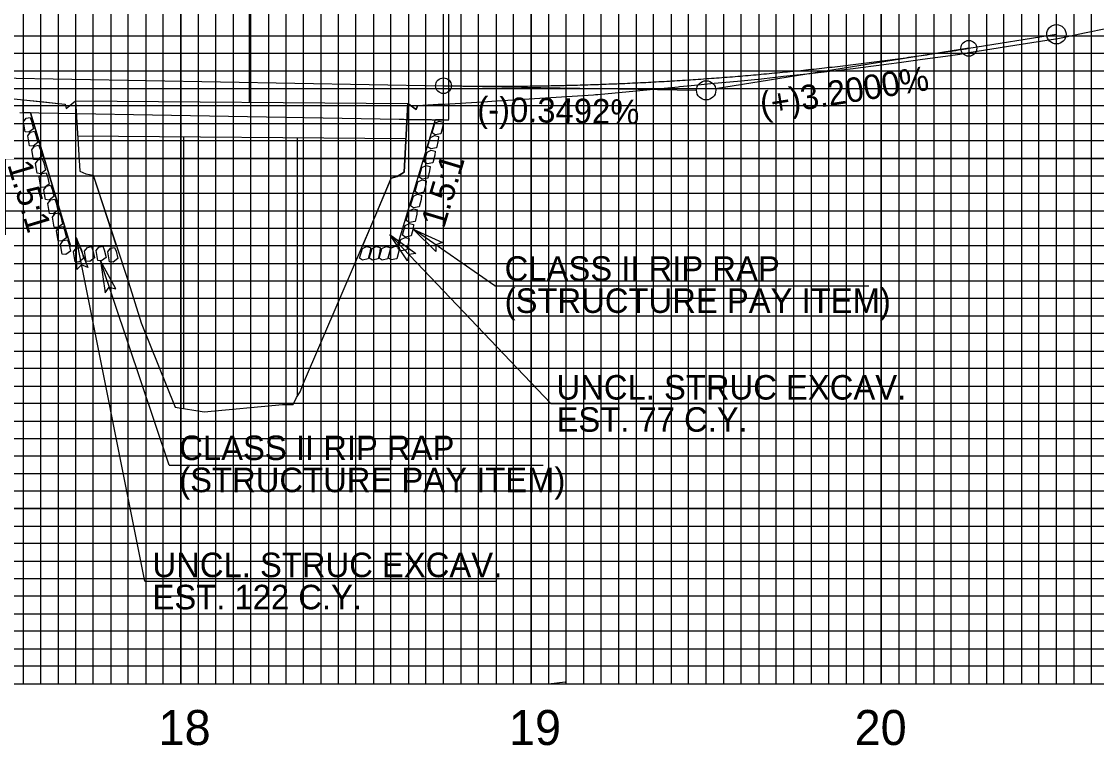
# Model space of a CAD drawing. Extents: x 573926 to 575610, y -51565 to -50465.
# Drawn here: x 574797.3 to 575104.2, y -51007.6 to -50800.8 of the extents above; entities that cross this region are included whole.
import ezdxf

# ---------------------------------------------------------------- set-up
doc = ezdxf.new("R2010")
doc.units = 0
for name, color, linetype in [('Default', 7, 'Continuous'), ('Exist Vertical Profile Ground Line', 7, 'Continuous'), ('Exist Vertical Profile Horizontal Axis Label Major', 7, 'Continuous'), ('Old_Level_1', 7, 'Continuous'), ('Prop Dimension', 7, 'Continuous'), ('Prop Dimension Text', 7, 'Continuous'), ('Prop Roadway Bridge', 7, 'Continuous'), ('Prop Terminator CELL', 7, 'Continuous'), ('Prop Vertical Profile Curve Label', 7, 'Continuous'), ('Prop Vertical Profile Grade', 7, 'Continuous'), ('Prop Vertical Profile Grade Label', 7, 'Continuous'), ('Prop VPI Label', 7, 'Continuous'), ('Sheet DOT Grid CELL', 7, 'Continuous'), ('Sheet Layout Profile Border Port 1', 7, 'Continuous'), ('Sheet Profile CELL', 7, 'Continuous'), ('Sheet Profile Grid Major CELL', 7, 'Continuous'), ('Sheet Profile Grid Middle CELL', 7, 'Continuous'), ('Sheet Profile Grid Minor CELL', 7, 'Continuous')]:
    doc.layers.add(name, color=color, linetype=linetype)

msp = doc.modelspace()

# ---------------------------------------------------------------- linework, layer by layer
at = {"layer": 'Default'}
for p, q in [((574812.68, -50823.46), (574907.64, -50824.23)), ((574813.3, -50833.46), (574907.08, -50834.23)), ((574843.68, -50911.41), (574843.68, -50833.71)), ((574876.14, -50907.67), (574876.14, -50833.97))]:
    msp.add_line(p, q, dxfattribs=at)
msp.add_lwpolyline([(574780.55, -50821.4), (574807.9, -50824.25), (574809.8, -50824.44), (574810.09, -50825.7), (574812.68, -50823.46), (574813.93, -50843.61), (574815.63, -50844.33), (574817.74, -50844.69), (574827.84, -50875.27), (574831.51, -50886.91), (574841.22, -50911.01), (574849.48, -50912.35), (574871.82, -50910.2), (574874.9, -50910.25), (574875.81, -50908.19), (574876.85, -50906.55), (574877.8, -50904.15), (574898.23, -50856.73), (574902.83, -50845.62), (574904.59, -50845.09), (574906.54, -50843.84), (574907.64, -50824.23), (574909.96, -50825.94), (574910.33, -50824.95), (574930.36, -50823.68), (574931.57, -50823.59), (574960.61, -50821.75), (574961.19, -50821.71), (574961.85, -50821.65), (574984.78, -50819.47), (574985.17, -50819.44), (574988.48, -50819.13)], dxfattribs=at)
at = {"layer": 'Exist Vertical Profile Ground Line'}
msp.add_lwpolyline([(574988.48, -50819.13), (574995.08, -50818.5), (575001.69, -50817.87), (575008.61, -50817.21), (575014.9, -50816.5), (575021.5, -50815.76), (575028.11, -50815.02), (575034.71, -50814.27), (575036.85, -50814.03), (575041.31, -50813.42), (575044.95, -50812.92), (575047.92, -50812.51), (575054.52, -50811.61), (575061.13, -50810.71), (575065.23, -50810.14), (575067.73, -50809.74), (575074.34, -50808.69), (575080.94, -50807.64), (575087.55, -50806.59), (575093.15, -50805.69), (575094.15, -50805.48), (575100.76, -50804.12), (575107.36, -50802.75)], dxfattribs=at)
at = {"layer": 'Old_Level_1'}
for p, q in [((574799.88, -50826.92), (574811.29, -50864.95)), ((574904.63, -50864.95), (574915.46, -50828.84)), ((574811.29, -50864.95), (574824.37, -50864.95)), ((574894.69, -50864.95), (574904.63, -50864.95))]:
    msp.add_line(p, q, dxfattribs=at)
for points in [[(574817.74, -50844.69), (574824.37, -50864.95), (574811.29, -50864.95), (574799.88, -50826.92), (574797.78, -50826.88), (574797.78, -50823.2), (574802.78, -50823.72), (574807.9, -50824.25), (574809.8, -50824.44), (574810.09, -50825.7), (574812.68, -50823.46), (574813.93, -50843.61), (574815.63, -50844.33)], [(574902.83, -50845.62), (574894.69, -50864.95), (574904.63, -50864.95), (574915.46, -50828.84), (574917.78, -50828.86), (574917.78, -50824.48), (574910.33, -50824.95), (574909.96, -50825.94), (574907.64, -50824.23), (574906.54, -50843.84), (574904.59, -50845.09)]]:
    msp.add_lwpolyline(points, close=True, dxfattribs=at)
for points in [[(574799.78, -50828.22), (574800.2, -50829.33), (574800.69, -50831.45), (574799.37, -50832.45), (574798.32, -50832.34), (574797.84, -50829.53), (574798.64, -50828.49), (574799.78, -50828.22)], [(574917.68, -50829.58), (574917.56, -50830.76), (574917.04, -50832.88), (574915.41, -50833.17), (574914.52, -50832.61), (574915.36, -50829.88), (574916.54, -50829.3), (574917.68, -50829.58)], [(574801.02, -50832.21), (574801.44, -50833.32), (574801.93, -50835.44), (574800.6, -50836.44), (574799.55, -50836.33), (574799.08, -50833.52), (574799.88, -50832.47), (574801.02, -50832.21)], [(574916.4, -50833.64), (574916.28, -50834.82), (574915.77, -50836.93), (574914.14, -50837.23), (574913.24, -50836.66), (574914.08, -50833.93), (574915.26, -50833.36), (574916.4, -50833.64)], [(574802.19, -50836.15), (574802.61, -50837.26), (574803.1, -50839.38), (574801.77, -50840.37), (574800.72, -50840.27), (574800.24, -50837.45), (574801.04, -50836.41), (574802.19, -50836.15)], [(574915.4, -50837.88), (574915.28, -50839.06), (574914.76, -50841.17), (574913.13, -50841.47), (574912.24, -50840.9), (574913.08, -50838.17), (574914.26, -50837.6), (574915.4, -50837.88)], [(574803.23, -50840.08), (574803.65, -50841.19), (574804.14, -50843.31), (574802.82, -50844.31), (574801.77, -50844.2), (574801.29, -50841.39), (574802.09, -50840.34), (574803.23, -50840.08)], [(574804.34, -50844.02), (574804.76, -50845.13), (574805.25, -50847.25), (574803.92, -50848.24), (574802.87, -50848.13), (574802.39, -50845.32), (574803.2, -50844.28), (574804.34, -50844.02)], [(574913.96, -50842.27), (574913.84, -50843.45), (574913.32, -50845.57), (574911.69, -50845.86), (574910.8, -50845.3), (574911.64, -50842.57), (574912.82, -50841.99), (574913.96, -50842.27)], [(574912.82, -50846.33), (574912.7, -50847.51), (574912.18, -50849.62), (574910.55, -50849.92), (574909.66, -50849.35), (574910.5, -50846.63), (574911.68, -50846.05), (574912.82, -50846.33)], [(574805.63, -50847.6), (574806.05, -50848.71), (574806.54, -50850.83), (574805.21, -50851.82), (574804.16, -50851.71), (574803.68, -50848.9), (574804.48, -50847.86), (574805.63, -50847.6)], [(574911.52, -50850.47), (574911.4, -50851.65), (574910.89, -50853.76), (574909.26, -50854.06), (574908.37, -50853.49), (574909.2, -50850.76), (574910.38, -50850.19), (574911.52, -50850.47)], [(574806.79, -50851.54), (574807.22, -50852.65), (574807.7, -50854.77), (574806.38, -50855.77), (574805.33, -50855.66), (574804.85, -50852.85), (574805.65, -50851.81), (574806.79, -50851.54)], [(574808.09, -50855.46), (574808.51, -50856.57), (574808.99, -50858.69), (574807.67, -50859.68), (574806.62, -50859.58), (574806.14, -50856.76), (574806.94, -50855.72), (574808.09, -50855.46)], [(574910.32, -50854.66), (574910.2, -50855.84), (574909.68, -50857.95), (574908.05, -50858.25), (574907.16, -50857.68), (574908, -50854.95), (574909.18, -50854.38), (574910.32, -50854.66)], [(574809.2, -50859.35), (574809.62, -50860.46), (574810.11, -50862.58), (574808.78, -50863.58), (574807.73, -50863.47), (574807.26, -50860.66), (574808.06, -50859.61), (574809.2, -50859.35)], [(574909.22, -50858.8), (574909.09, -50859.98), (574908.58, -50862.09), (574906.95, -50862.39), (574906.06, -50861.82), (574906.89, -50859.09), (574908.07, -50858.52), (574909.22, -50858.8)], [(574907.97, -50862.79), (574907.84, -50863.97), (574907.33, -50866.08), (574905.7, -50866.38), (574904.81, -50865.81), (574905.64, -50863.08), (574906.82, -50862.51), (574907.97, -50862.79)], [(574810.4, -50863.17), (574810.82, -50864.28), (574811.3, -50866.4), (574809.98, -50867.4), (574808.93, -50867.29), (574808.45, -50864.48), (574809.25, -50863.43), (574810.4, -50863.17)], [(574814.11, -50865.34), (574814.53, -50866.45), (574815.01, -50868.57), (574813.69, -50869.57), (574812.64, -50869.46), (574812.16, -50866.65), (574812.96, -50865.6), (574814.11, -50865.34)], [(574817.26, -50865.13), (574817.68, -50866.24), (574818.17, -50868.36), (574816.84, -50869.35), (574815.79, -50869.25), (574815.32, -50866.43), (574816.12, -50865.39), (574817.26, -50865.13)], [(574820.53, -50864.98), (574820.95, -50866.09), (574821.44, -50868.21), (574820.12, -50869.2), (574819.07, -50869.1), (574818.59, -50866.28), (574819.39, -50865.24), (574820.53, -50864.98)], [(574823.87, -50865.34), (574824.29, -50866.44), (574824.78, -50868.57), (574823.45, -50869.56), (574822.4, -50869.45), (574821.93, -50866.64), (574822.73, -50865.6), (574823.87, -50865.34)], [(574896.97, -50865.37), (574896.85, -50866.55), (574896.33, -50868.66), (574894.7, -50868.96), (574893.81, -50868.39), (574894.65, -50865.66), (574895.83, -50865.09), (574896.97, -50865.37)], [(574899.74, -50865.37), (574899.62, -50866.55), (574899.11, -50868.66), (574897.48, -50868.96), (574896.58, -50868.39), (574897.42, -50865.66), (574898.6, -50865.09), (574899.74, -50865.37)], [(574902.55, -50865.37), (574902.43, -50866.55), (574901.91, -50868.66), (574900.29, -50868.96), (574899.39, -50868.39), (574900.23, -50865.66), (574901.41, -50865.09), (574902.55, -50865.37)], [(574905.13, -50865.29), (574905.01, -50866.47), (574904.49, -50868.59), (574902.86, -50868.88), (574901.97, -50868.32), (574902.8, -50865.59), (574903.99, -50865.01), (574905.13, -50865.29)]]:
    msp.add_lwpolyline(points, dxfattribs=at)
at = {"layer": 'Prop Dimension'}
for p, q in [((575092.78, -50804.5), (575092.78, -50624.54)), ((574919.34, -50819.11), (574919.34, -50664.95)), ((574862.33, -50762.43), (574862.33, -50823.86)), ((574832.53, -50960.67), (574812.89, -50862.56)), ((574902.47, -50861.64), (574948.45, -50909.93)), ((574932.41, -50876.34), (574909.12, -50860.12)), ((574839.5, -50927.53), (574819.85, -50869.19)), ((574932.41, -50876.34), (575039.19, -50876.34)), ((574948.45, -50909.93), (575048, -50909.93)), ((574839.5, -50927.53), (574946.28, -50927.53)), ((574832.53, -50960.67), (574932.69, -50960.67))]:
    msp.add_line(p, q, dxfattribs=at)
at = {"layer": 'Prop Roadway Bridge'}
for p, q in [((574919.34, -50828.87), (574919.34, -50819.11)), ((574796.84, -50826.87), (574905.11, -50828.76))]:
    msp.add_line(p, q, dxfattribs=at)
msp.add_open_spline([(574905.12, -50828.76), (574906.3, -50828.78), (574907.47, -50828.79), (574908.64, -50828.81), (574909.82, -50828.83), (574911, -50828.84), (574912.18, -50828.86), (574913.35, -50828.87), (574914.53, -50828.88), (574915.71, -50828.89), (574916.89, -50828.89), (574918.07, -50828.9), (574919.25, -50828.9), (574919.28, -50828.9), (574919.31, -50828.9), (574919.34, -50828.9)], degree=3, dxfattribs=at)
at = {"layer": 'Prop Terminator CELL'}
for points in [[(574813.13, -50871.69), (574812.89, -50862.56), (574816.23, -50871.12), (574814.44, -50870.31)], [(574813.13, -50871.69), (574812.89, -50862.56), (574816.23, -50871.12), (574814.44, -50870.31)], [(574907.56, -50869.23), (574902.47, -50861.64), (574909.87, -50867.09), (574907.92, -50867.36)], [(574907.56, -50869.23), (574902.47, -50861.64), (574909.87, -50867.09), (574907.92, -50867.36)], [(574915.62, -50866.54), (574909.12, -50860.12), (574917.46, -50863.98), (574915.6, -50864.64)], [(574824.2, -50877.22), (574819.85, -50869.19), (574821.23, -50878.28), (574822.38, -50876.67)]]:
    msp.add_lwpolyline(points, close=True, dxfattribs=at)
at = {"layer": 'Prop Vertical Profile Curve Label'}
for centre in [(575067.78, -50808.5), (574917.78, -50819.19)]:
    msp.add_circle(centre, 2.25, dxfattribs=at)
at = {"layer": 'Prop Vertical Profile Grade'}
for p, q in [((575067.78, -50808.5), (575092.78, -50804.5)), ((574787.78, -50816.92), (574917.78, -50819.19))]:
    msp.add_line(p, q, dxfattribs=at)
msp.add_spline([(574917.78, -50819.19), (574920.78, -50819.23), (574923.78, -50819.27), (574926.78, -50819.3), (574929.78, -50819.31), (574932.78, -50819.32), (574935.78, -50819.31), (574938.78, -50819.29), (574941.78, -50819.27), (574944.78, -50819.23), (574947.78, -50819.18), (574950.78, -50819.12), (574953.78, -50819.05), (574956.78, -50818.97), (574959.78, -50818.88), (574962.78, -50818.77), (574965.78, -50818.66), (574968.78, -50818.54), (574971.78, -50818.4), (574974.78, -50818.26), (574977.78, -50818.1), (574980.78, -50817.94), (574983.78, -50817.76), (574986.78, -50817.58), (574989.78, -50817.38), (574992.78, -50817.17), (574995.78, -50816.95), (574998.78, -50816.72), (575001.78, -50816.48), (575004.78, -50816.23), (575007.78, -50815.97), (575010.78, -50815.69), (575013.78, -50815.41), (575016.78, -50815.12), (575019.78, -50814.81), (575022.78, -50814.5), (575025.78, -50814.17), (575028.78, -50813.84), (575031.78, -50813.49), (575034.78, -50813.13), (575037.78, -50812.76), (575040.78, -50812.39), (575043.78, -50812), (575046.78, -50811.6), (575049.78, -50811.18), (575052.78, -50810.76), (575055.78, -50810.33), (575058.78, -50809.89), (575061.78, -50809.44), (575064.78, -50808.97), (575067.78, -50808.5)], degree=3, dxfattribs=at)
at = {"layer": 'Prop VPI Label'}
for p, q in [((575067.78, -50808.5), (574995.49, -50820.06)), ((574917.78, -50819.19), (574990.03, -50820.45))]:
    msp.add_line(p, q, dxfattribs=at)
for centre in [(575092.78, -50804.5), (574992.78, -50820.5)]:
    msp.add_circle(centre, 2.75, dxfattribs=at)
at = {"layer": 'Sheet DOT Grid CELL'}
for p, q in [((574842.78, -50989.95), (574842.78, -50489.95)), ((574892.78, -50989.95), (574892.78, -50489.95)), ((574942.78, -50989.95), (574942.78, -50489.95)), ((574992.78, -50989.95), (574992.78, -50489.95)), ((575042.78, -50989.95), (575042.78, -50489.95)), ((575092.78, -50989.95), (575092.78, -50489.95)), ((575592.78, -50839.95), (574092.78, -50839.95)), ((575592.78, -50889.95), (574092.78, -50889.95)), ((575592.78, -50939.95), (574092.78, -50939.95))]:
    msp.add_line(p, q, dxfattribs=at)
at = {"layer": 'Sheet Layout Profile Border Port 1'}
msp.add_lwpolyline([(574142.78, -50489.95), (574142.78, -50989.95), (575542.78, -50989.95), (575542.78, -50627.5), (575392.73, -50627.5), (575392.73, -50489.95)], close=True, dxfattribs=at)
at = {"layer": 'Sheet Profile CELL'}
msp.add_line((574092.78, -50989.95), (575592.78, -50989.95), dxfattribs=at)
at = {"layer": 'Sheet Profile Grid Major CELL'}
for points in [[(574542.78, -50989.95), (574592.78, -50989.95), (574592.78, -50489.95), (574642.78, -50489.95), (574642.78, -50989.95), (574692.78, -50989.95), (574692.78, -50489.95), (574742.78, -50489.95), (574742.78, -50989.95), (574792.78, -50989.95), (574792.78, -50489.95), (574842.78, -50489.95), (574842.78, -50989.95), (574892.78, -50989.95), (574892.78, -50489.95), (574942.78, -50489.95), (574942.78, -50989.95), (574992.78, -50989.95), (574992.78, -50489.95), (575042.78, -50489.95), (575042.78, -50989.95), (575092.78, -50989.95), (575092.78, -50489.95), (575142.78, -50489.95)], [(575592.78, -50789.95), (574092.78, -50789.95), (574092.78, -50839.95), (575592.78, -50839.95)], [(575592.78, -50889.95), (574092.78, -50889.95), (574092.78, -50889.95), (574092.78, -50939.95), (575592.78, -50939.95)]]:
    msp.add_lwpolyline(points, dxfattribs=at)
at = {"layer": 'Sheet Profile Grid Middle CELL'}
for points in [[(574767.78, -50989.95), (574817.78, -50989.95), (574817.78, -50489.95), (574867.78, -50489.95), (574867.78, -50989.95), (574917.78, -50989.95), (574917.78, -50489.95), (574967.78, -50489.95), (574967.78, -50989.95), (575017.78, -50989.95), (575017.78, -50489.95), (575067.78, -50489.95), (575067.78, -50989.95), (575117.78, -50989.95)], [(575592.78, -50764.95), (574092.78, -50764.95), (574092.78, -50814.95), (575592.78, -50814.95)], [(575592.78, -50864.95), (574092.78, -50864.95), (574092.78, -50914.95), (575592.78, -50914.95)], [(575592.78, -50964.95), (574092.78, -50964.95)]]:
    msp.add_lwpolyline(points, dxfattribs=at)
at = {"layer": 'Sheet Profile Grid Minor CELL'}
for p, q in [((574142.78, -50804.95), (575542.78, -50804.95)), ((575542.78, -50809.95), (574142.78, -50809.95)), ((574142.78, -50819.95), (575542.78, -50819.95)), ((575542.78, -50824.95), (574142.78, -50824.95)), ((574142.78, -50829.95), (575542.78, -50829.95)), ((575542.78, -50834.95), (574142.78, -50834.95)), ((574142.78, -50844.95), (575542.78, -50844.95)), ((575542.78, -50849.95), (574142.78, -50849.95)), ((574142.78, -50854.95), (575542.78, -50854.95)), ((575542.78, -50859.95), (574142.78, -50859.95)), ((574142.78, -50869.95), (575542.78, -50869.95)), ((575542.78, -50874.95), (574142.78, -50874.95)), ((575542.78, -50879.95), (574142.78, -50879.95)), ((575542.78, -50884.95), (574142.78, -50884.95)), ((574142.78, -50894.95), (575542.78, -50894.95)), ((575542.78, -50899.95), (574142.78, -50899.95)), ((574142.78, -50904.95), (575542.78, -50904.95)), ((575542.78, -50909.95), (574142.78, -50909.95)), ((574142.78, -50919.95), (575542.78, -50919.95)), ((575542.78, -50924.95), (574142.78, -50924.95)), ((574142.78, -50929.95), (575542.78, -50929.95)), ((575542.78, -50934.95), (574142.78, -50934.95)), ((574142.78, -50944.95), (575542.78, -50944.95)), ((575542.78, -50949.95), (574142.78, -50949.95)), ((574142.78, -50954.95), (575542.78, -50954.95)), ((575542.78, -50959.95), (574142.78, -50959.95)), ((574142.78, -50969.95), (575542.78, -50969.95)), ((575542.78, -50974.95), (574142.78, -50974.95)), ((574142.78, -50979.95), (575542.78, -50979.95))]:
    msp.add_line(p, q, dxfattribs=at)
for points in [[(574797.78, -50489.95), (574797.78, -50989.95), (574797.78, -50989.95), (574802.78, -50989.95), (574802.78, -50489.95)], [(574807.78, -50489.95), (574807.78, -50989.95), (574812.78, -50989.95), (574812.78, -50489.95)], [(574822.78, -50489.95), (574822.78, -50989.95), (574827.78, -50989.95), (574827.78, -50489.95)], [(574832.78, -50489.95), (574832.78, -50989.95), (574837.78, -50989.95), (574837.78, -50489.95)], [(574847.78, -50489.95), (574847.78, -50989.95), (574852.78, -50989.95), (574852.78, -50489.95)], [(574857.78, -50489.95), (574857.78, -50989.95), (574862.78, -50989.95), (574862.78, -50489.95)], [(574872.78, -50489.95), (574872.78, -50989.95), (574877.78, -50989.95), (574877.78, -50489.95)], [(574882.78, -50489.95), (574882.78, -50989.95), (574887.78, -50989.95), (574887.78, -50489.95)], [(574897.78, -50489.95), (574897.78, -50989.95), (574902.78, -50989.95), (574902.78, -50489.95)], [(574907.78, -50489.95), (574907.78, -50989.95), (574912.78, -50989.95), (574912.78, -50489.95)], [(574922.78, -50489.95), (574922.78, -50989.95), (574927.78, -50989.95), (574927.78, -50489.95)], [(574932.78, -50489.95), (574932.78, -50989.95), (574937.78, -50989.95), (574937.78, -50489.95)], [(574947.78, -50489.95), (574947.78, -50989.95), (574952.48, -50989.4), (574952.78, -50989.95), (574952.78, -50489.95)], [(574957.78, -50489.95), (574957.78, -50989.95), (574962.78, -50989.95), (574962.78, -50489.95)], [(574972.78, -50489.95), (574972.78, -50989.95), (574977.78, -50989.95)], [(574977.78, -50989.95), (574977.78, -50489.95)], [(574982.78, -50489.95), (574982.78, -50989.95), (574987.78, -50989.95), (574987.78, -50489.95)], [(574997.78, -50489.95), (574997.78, -50989.95), (575002.78, -50989.95), (575002.78, -50489.95)], [(575007.78, -50489.95), (575007.78, -50989.95), (575012.78, -50989.95), (575012.78, -50489.95)], [(575022.78, -50489.95), (575022.78, -50989.95), (575027.78, -50989.95), (575027.78, -50489.95)], [(575032.78, -50489.95), (575032.78, -50989.95), (575037.78, -50989.95), (575037.78, -50489.95)], [(575047.78, -50489.95), (575047.78, -50989.95), (575052.78, -50989.95), (575052.78, -50489.95)], [(575057.78, -50489.95), (575057.78, -50989.95), (575062.78, -50989.95), (575062.78, -50489.95)], [(575072.78, -50489.95), (575072.78, -50989.95), (575077.78, -50989.95), (575077.78, -50489.95)], [(575082.78, -50489.95), (575082.78, -50989.95), (575087.78, -50989.95), (575087.78, -50489.95)], [(575097.78, -50489.95), (575097.78, -50989.95), (575102.78, -50989.95), (575102.78, -50489.95)], [(575542.78, -50984.95), (574142.78, -50984.95)]]:
    msp.add_lwpolyline(points, dxfattribs=at)

# ---------------------------------------------------------------- texts
at = {"layer": 'Exist Vertical Profile Horizontal Axis Label Major'}
for s, p in [('18', (574836.44, -51007.45)), ('19', (574936.48, -51007.45)), ('20', (575035.16, -51007.45))]:
    msp.add_text(s, height=10, dxfattribs=at).set_placement(p)
at = {"layer": 'Old_Level_1'}
for rotation, p in [(286.6992, (574793.22, -50841.7)), (73.3008, (574917.95, -50860.15))]:
    msp.add_text('1.5:1', height=7, rotation=rotation, dxfattribs=at).set_placement(p)
at = {"layer": 'Prop Dimension Text'}
for s, p in [('CLASS II RIP RAP', (574935.25, -50874.89)), ('(STRUCTURE PAY ITEM)', (574935.25, -50884.06)), ('UNCL. STRUC EXCAV.', (574950.05, -50908.81)), ('EST. 77 C.Y.', (574950.05, -50917.99)), ('CLASS II RIP RAP', (574842.34, -50926.08)), ('(STRUCTURE PAY ITEM)', (574842.34, -50935.25)), ('UNCL. STRUC EXCAV.', (574834.7, -50959.52)), ('EST. 122 C.Y.', (574834.7, -50968.7))]:
    msp.add_text(s, height=7, dxfattribs=at).set_placement(p)
at = {"layer": 'Prop Vertical Profile Grade Label'}
for s, rotation, p in [('(+)3.2000%', 9.0903, (575008.71, -50828.07)), ('(-)0.3492%', 358.9997, (574927.37, -50829.36))]:
    msp.add_text(s, height=7, rotation=rotation, dxfattribs=at).set_placement(p)

doc.saveas('drawing.dxf')
